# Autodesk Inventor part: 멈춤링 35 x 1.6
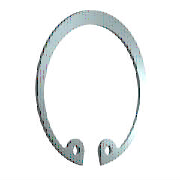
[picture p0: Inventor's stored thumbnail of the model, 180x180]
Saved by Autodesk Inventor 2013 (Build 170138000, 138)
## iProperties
IsCustomPart: 1
Created: 2012-02
Part Number: 멈춤링 35 x 1.6
Material: 강철, 연강
Description: 리테이닝 링(C형)
Document SubType Name: Modeling
Standard: KS B 1336
Designer: mduedu
Standards Organization: KS
Language: ko-KR
Size Designation: 35x1.6
Categories: <MemberInstance><Categories><Category DisplayName="샤프트 부품" InternalName="7f7aeb1f-a693-4053-b835-cee3144e0d98" Mnemonic="SHFT"><Category DisplayName="써클립" Inter
Density: 1 g/cm^3
Author: mduedu
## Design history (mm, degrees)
sketch "스케치1"
  geometry: L1 (0, 15.113)-(0, -73.177) reference; L2 (-45.5, 0)-(45.5, 0) reference; L3 (-4.964, 1)-(1.502, 1); L4 (0, -2.5)-(-5.307, -2.5); L5 (0, -17.5)-(-8.583, -33.888); L6 (-8.583, -33.888)-(-21.772, -26.981); L7 (-7.377, -31.585)-(-17.631, -26.214); L8 (-5.162, -32.745)-(-6.29, -34.898); L9 (5.162, -32.745)-(6.29, -34.898); C1 r 1.25 at (-7.377, -31.585); C2 r 1.25 at (7.377, -31.585); A1 r 15.875 centre (0, -18.375) between (11.82, -28.972) and (-11.82, -28.972); A2 r 18.5 centre (0, -17.5) between (6.29, -34.898) and (-6.29, -34.898); A3 r 2.5 centre (-7.377, -31.585) between (-5.162, -32.745) and (-8.668, -29.444); A4 r 2.5 centre (-9.959, -27.303) between (-11.82, -28.972) and (-8.668, -29.444); A5 r 2.5 centre (9.959, -27.303) between (8.668, -29.444) and (11.82, -28.972); A6 r 2.5 centre (7.377, -31.585) between (8.668, -29.444) and (5.162, -32.745); 3 further points
  constraints: 15 point on circle, 14 end point, 9 symmetric about line, 8 centre point, 6 tangent, 4 coincident, 4 point on line, 3 perpendicular, 1 parallel, 4 other
  dimensions: "d8" = 0.875 distance of A1.centre L5.start (= 0.25 x SRB1); "d38" = 3.5 distance between parallel lines of L4 L3 (= SRB1); "d39" = 17.5 distance from line of L5.start L2 (= 0.5 x WD); "d43" = 18.5 radius of A2 (= 0.5 x ND); "d45" = 2.6 distance between parallel lines of L7 L6 (= 0.5 x SRB2); "d46" = 2.5 radius of A4 (= SD5); "d47" = 6.29 distance from line of L1 L8.end (= 0.17 x ND); "d48" = 2.5 diameter of C1 (= SD5); "d49" = 2.5 radius of A3 (= SD5)
extrude "본체" new body sketch "스케치1" distance "d2" = 1.6 (= SD); taper "d3" = 0 deg
workaxis "Work Axis1"
workaxis "Work Axis2"
workplane "Work Plane1"
body "Solid1"
other parameters: "WD" = 35 [user parameter; used in 3 equation terms], "SD" = 1.6 [user parameter; used in 1 equation term], "SRB1" = 3.5 [user parameter; used in 2 equation terms], "ND" = 37 [user parameter; used in 2 equation terms], "SRB2" = 5.2 [user parameter; used in 1 equation term], "SD5" = 2.5 [user parameter; used in 3 equation terms], "d50" = 0, "d51" = 0, "d52" = 0, "d53" = 0, "WDMIN" = 34 [user parameter], "SD6" = 37.8 [user parameter], "WDMAX" = 35 (= WD) [user parameter], "NND" = 35 (= WD) [user parameter]
